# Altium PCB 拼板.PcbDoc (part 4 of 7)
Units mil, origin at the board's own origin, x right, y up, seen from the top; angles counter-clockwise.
Board outline 3630.03 x 5330.03 mil, 2 copper layers (Top Layer, Bottom Layer); 416 components, 35 nets, 1936 pads, 800 vias.
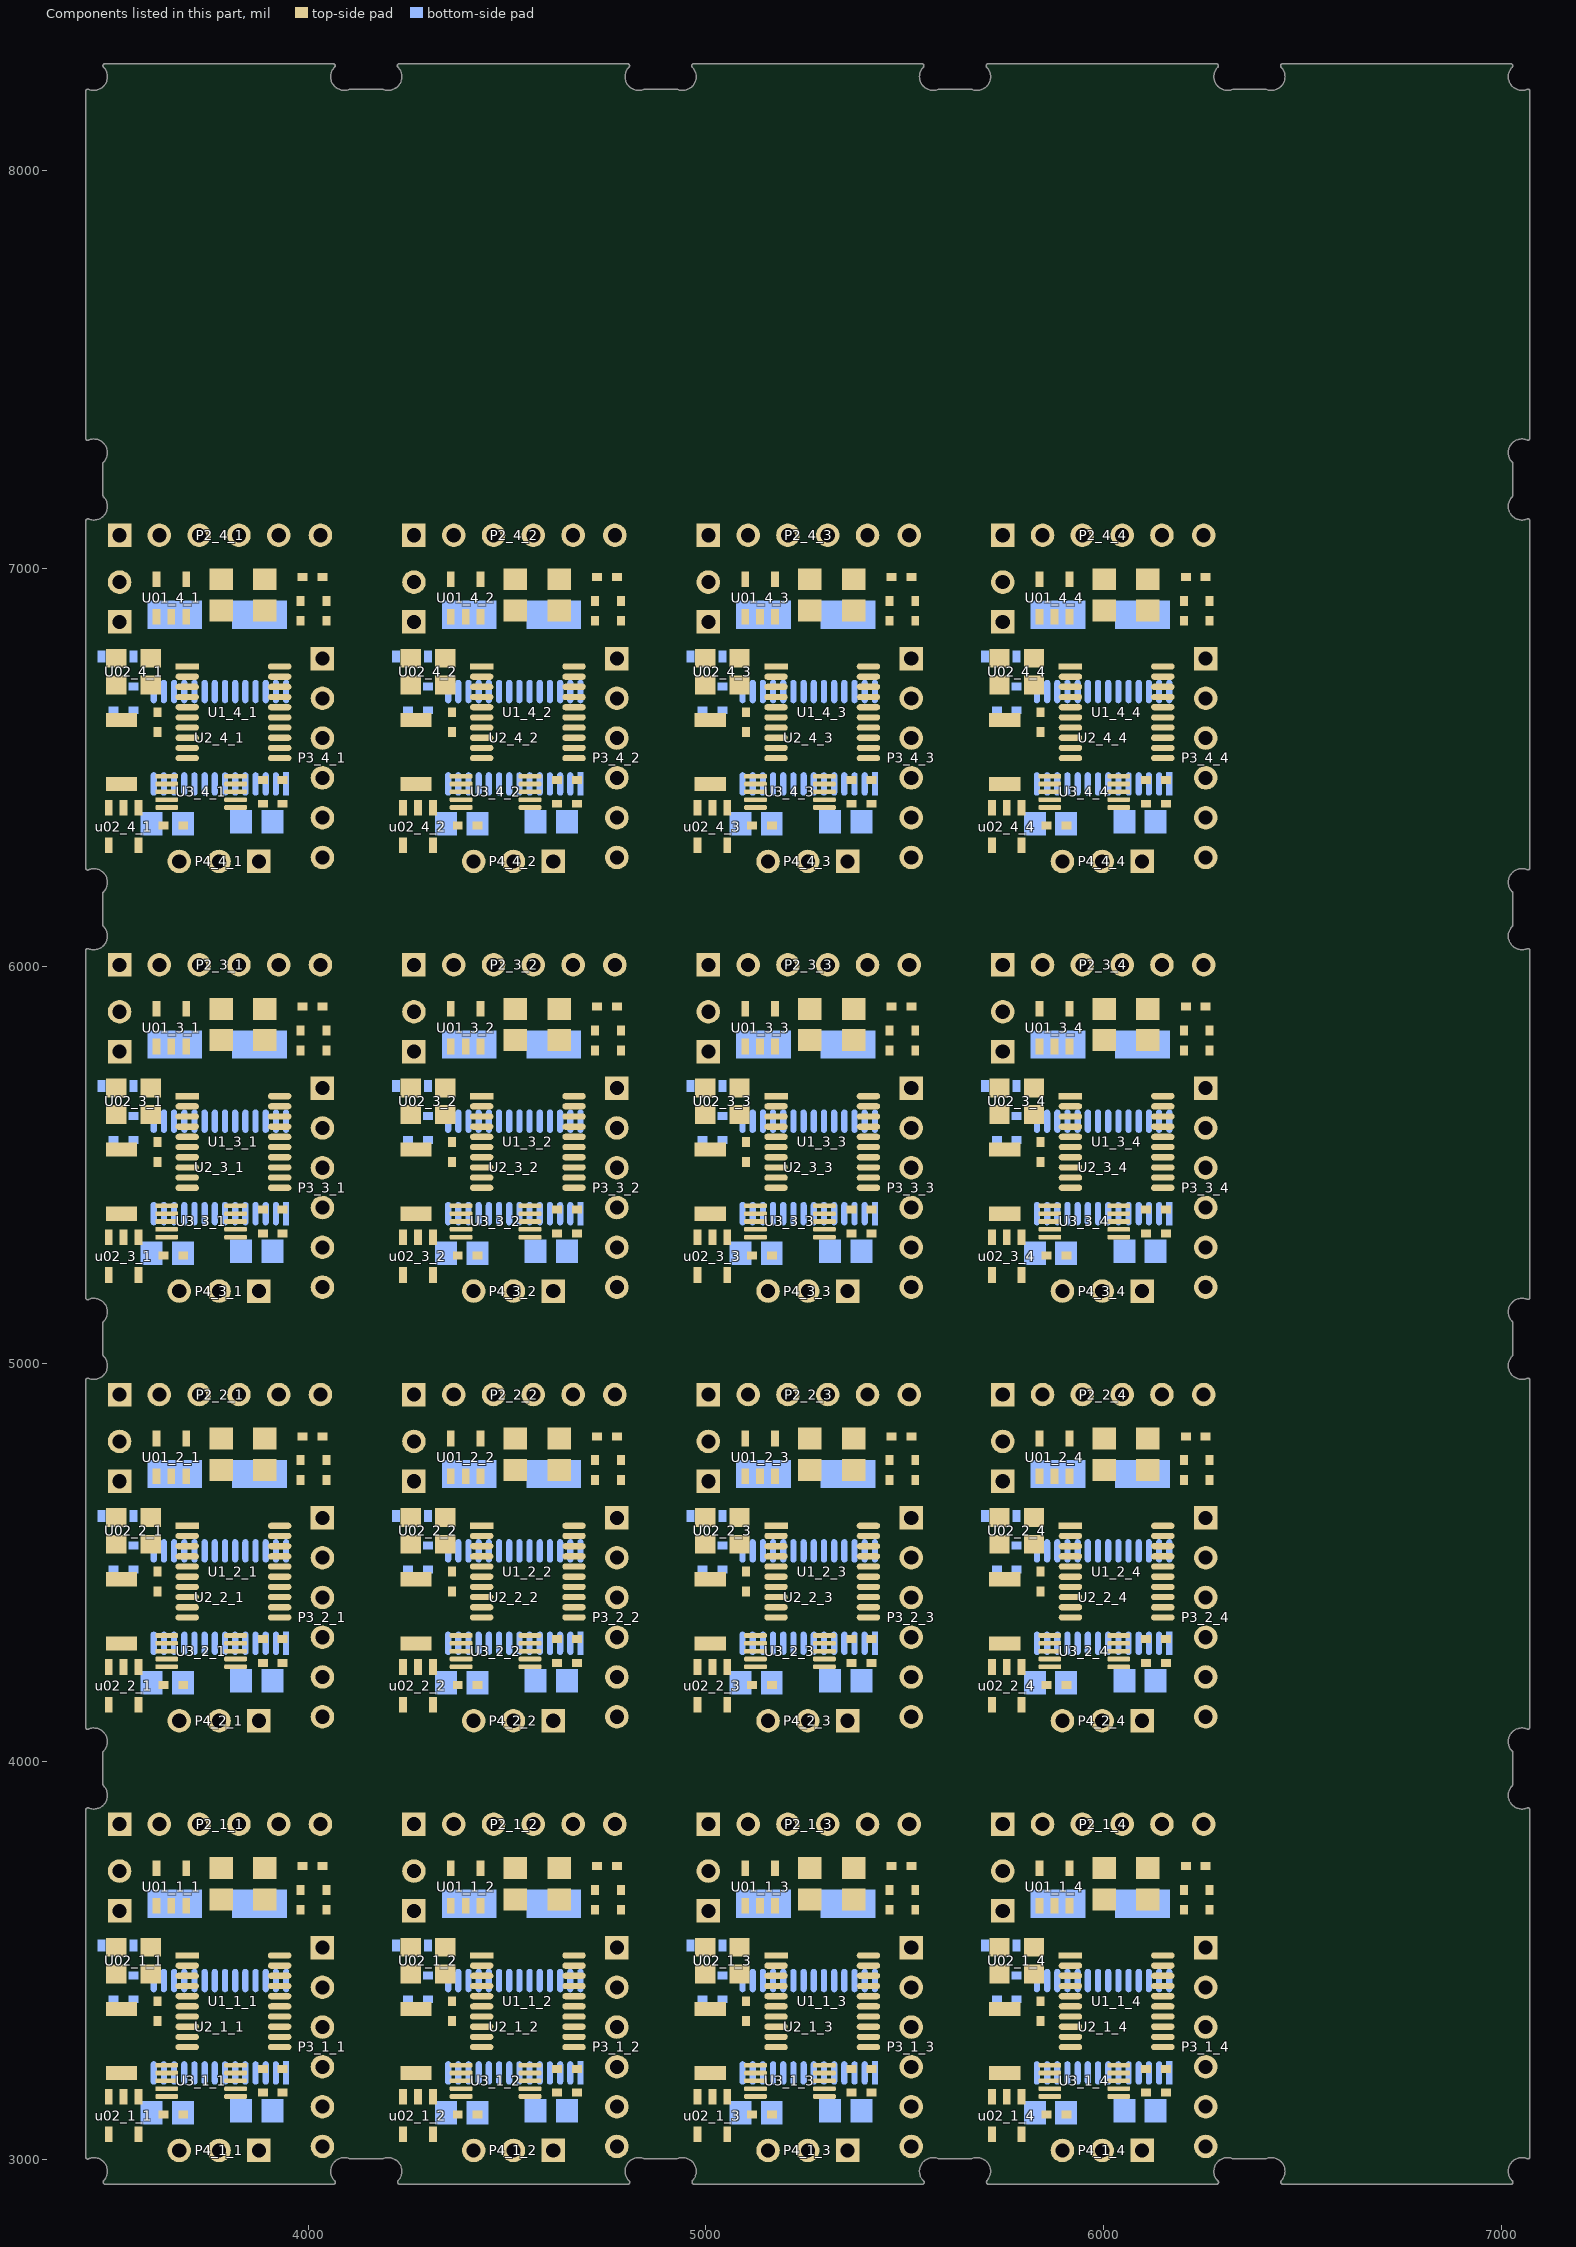
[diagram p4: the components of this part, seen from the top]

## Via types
v1: diameter 24, hole 24, Top Layer to Bottom Layer, 480 vias
v2: diameter 20, hole 10, Top Layer to Bottom Layer, 240 vias
v3: diameter 36, hole 20, Top Layer to Bottom Layer, 48 vias
v4: diameter 32, hole 16, Top Layer to Bottom Layer, 32 vias

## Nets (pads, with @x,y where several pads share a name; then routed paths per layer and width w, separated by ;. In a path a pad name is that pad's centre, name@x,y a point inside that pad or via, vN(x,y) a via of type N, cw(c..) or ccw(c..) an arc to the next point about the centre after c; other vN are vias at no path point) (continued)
copper on no net: (continued)
  Top Layer w16: 3498.66,3158.02 3500.51,3156.18 3500.51,3117.83 3536.07,3082.27 ; 3498.66,4238.02 3500.51,4236.18 3500.51,4197.83 3536.07,4162.27 ; 3498.66,5318.02 3500.51,5316.18 3500.51,5277.83 3536.07,5242.27 ; 3498.66,6398.02 3500.51,6396.18 3500.51,6357.83 3536.07,6322.27 ; 3517.76,3533.57 3519.73,3533.57 3556.35,3570.19 3695.64,3570.19 3779.1,3653.65 3781.07,3653.65 ; 3517.76,4613.57 3519.73,4613.57 3556.35,4650.19 3695.64,4650.19 3779.1,4733.65 3781.07,4733.65 ; 3517.76,5693.57 3519.73,5693.57 3556.35,5730.19 3695.64,5730.19 3779.1,5813.65 3781.07,5813.65 ; 3517.76,6773.57 3519.73,6773.57 3556.35,6810.19 3695.64,6810.19 3779.1,6893.65 3781.07,6893.65 ; 3531.07,3217.31 3531.26,3217.51 3536.07,3217.51 3596.07,3217.51 ; 3531.07,4297.31 3531.26,4297.51 3536.07,4297.51 3596.07,4297.51 ; 3531.07,5377.31 3531.26,5377.51 3536.07,5377.51 3596.07,5377.51 ; 3531.07,6457.31 3531.26,6457.51 3536.07,6457.51 3596.07,6457.51 ; 3535.69,3082.64 3571.63,3118.58 3571.63,3156.18 3573.47,3158.02 ; 3535.69,4162.64 3571.63,4198.58 3571.63,4236.18 3573.47,4238.02 ; 3535.69,5242.64 3571.63,5278.58 3571.63,5316.18 3573.47,5318.02 ; 3535.69,6322.64 3571.63,6358.58 3571.63,6396.18 3573.47,6398.02 ; 3536.07,3078.02 3536.07,3035.22 3598.27,2973.02 3906.07,2973.02 ; 3536.07,4158.02 3536.07,4115.22 3598.27,4053.02 3906.07,4053.02 ; 3536.07,5238.02 3536.07,5195.22 3598.27,5133.02 3906.07,5133.02 ; 3536.07,6318.02 3536.07,6275.22 3598.27,6213.02 3906.07,6213.02 ; 3618.66,3732.51 3618.66,3742.35 3649.33,3773.02 3738.47,3773.02 3779.1,3732.39 3781.07,3732.39 ; 3618.66,4812.51 3618.66,4822.35 3649.33,4853.02 3738.47,4853.02 3779.1,4812.39 3781.07,4812.39 ; 3618.66,5892.51 3618.66,5902.35 3649.33,5933.02 3738.47,5933.02 3779.1,5892.39 3781.07,5892.39 ; 3618.66,6972.51 3618.66,6982.35 3649.33,7013.02 3738.47,7013.02 3779.1,6972.39 3781.07,6972.39 ; 3623.91,3179.12 3612.25,3179.12 3602.91,3188.46 3602.91,3210.67 3596.07,3217.51 ; 3623.91,3217.51 3596.07,3217.51 ; 3623.91,4259.12 3612.25,4259.12 3602.91,4268.46 3602.91,4290.67 3596.07,4297.51 ; 3623.91,4297.51 3596.07,4297.51 ; 3623.91,5339.12 3612.25,5339.12 3602.91,5348.46 3602.91,5370.67 3596.07,5377.51 ; 3623.91,5377.51 3596.07,5377.51 ; 3623.91,6419.12 3612.25,6419.12 3602.91,6428.46 3602.91,6450.67 3596.07,6457.51 ; 3623.91,6457.51 3596.07,6457.51 ; 3665,3177.56 3676.65,3177.56 3686,3168.21 3686,3113.09 3686.07,3113.02 3688.07,3115.02 3703.26,3115.02 3785.48,3197.24 3790.63,3197.24 ; 3665,3198.56 3686.25,3198.56 3708.25,3176.56 v4(3713.77,3176.56) ; 3665,4257.56 3676.65,4257.56 3686,4248.21 3686,4193.09 3686.07,4193.02 3688.07,4195.02 3703.26,4195.02 3785.48,4277.24 3790.63,4277.24 ; 3665,4278.56 3686.25,4278.56 3708.25,4256.56 v4(3713.77,4256.56) ; 3665,5337.56 3676.65,5337.56 3686,5328.21 3686,5273.09 3686.07,5273.02 3688.07,5275.02 3703.26,5275.02 3785.48,5357.24 3790.63,5357.24 ; 3665,5358.56 3686.25,5358.56 3708.25,5336.56 v4(3713.77,5336.56) ; 3665,6417.56 3676.65,6417.56 3686,6408.21 3686,6353.09 3686.07,6353.02 3688.07,6355.02 3703.26,6355.02 3785.48,6437.24 3790.63,6437.24 ; 3665,6438.56 3686.25,6438.56 3708.25,6416.56 v4(3713.77,6416.56) ; 3696.07,3436.25 3696.19,3436.38 3733.08,3436.38 3778.07,3481.36 3778.07,3650.65 3781.07,3653.65 ; 3696.07,4516.25 3696.19,4516.38 3733.08,4516.38 3778.07,4561.36 3778.07,4730.65 3781.07,4733.65 ; 3696.07,5596.25 3696.19,5596.38 3733.08,5596.38 3778.07,5641.36 3778.07,5810.65 3781.07,5813.65 ; 3696.07,6676.25 3696.19,6676.38 3733.08,6676.38 3778.07,6721.36 3778.07,6890.65 3781.07,6893.65 ; v4(3831.07,3128.02) 3834.13,3131.08 3841.22,3131.08 3860.57,3150.43 3860.57,3168.65 3851.19,3178.02 3841.07,3178.02 ; v4(3831.07,4208.02) 3834.13,4211.08 3841.22,4211.08 3860.57,4230.43 3860.57,4248.65 3851.19,4258.02 3841.07,4258.02 ; v4(3831.07,5288.02) 3834.13,5291.08 3841.22,5291.08 3860.57,5310.43 3860.57,5328.65 3851.19,5338.02 3841.07,5338.02 ; v4(3831.07,6368.02) 3834.13,6371.08 3841.22,6371.08 3860.57,6390.43 3860.57,6408.65 3851.19,6418.02 3841.07,6418.02 ; 3891.07,3732.39 3893.03,3732.39 3995.43,3834.78 4022.83,3834.78 4031.07,3843.02 ; 3891.07,4812.39 3893.03,4812.39 3995.43,4914.78 4022.83,4914.78 4031.07,4923.02 ; 3891.07,5892.39 3893.03,5892.39 3995.43,5994.78 4022.83,5994.78 4031.07,6003.02 ; 3891.07,6972.39 3893.03,6972.39 3995.43,7074.78 4022.83,7074.78 4031.07,7083.02 ; 3911.07,2973.02 3981.07,2973.02 4036.07,3028.02 ; 3911.07,4053.02 3981.07,4053.02 4036.07,4108.02 ; 3911.07,5133.02 3981.07,5133.02 4036.07,5188.02 ; 3911.07,6213.02 3981.07,6213.02 4036.07,6268.02 ; 4036.07,3033.02 4088.07,3085.02 4088.07,3158.02 4088.07,3733.02 4061.07,3760.02 4061.07,3761.02 4011.57,3761.02 3990.57,3740.02 3988.07,3740.02 3986.07,3738.02 3983.57,3738.02 3981.07,3735.52 3981.07,3675.52 3979.07,3673.52 3976.57,3673.52 3956.7,3653.65 3891.07,3653.65 3781.07,3653.65 ; 4036.07,4113.02 4088.07,4165.02 4088.07,4238.02 4088.07,4813.02 4061.07,4840.02 4061.07,4841.02 4011.57,4841.02 3990.57,4820.02 3988.07,4820.02 3986.07,4818.02 3983.57,4818.02 3981.07,4815.52 3981.07,4755.52 3979.07,4753.52 3976.57,4753.52 3956.7,4733.65 3891.07,4733.65 3781.07,4733.65 ; 4036.07,5193.02 4088.07,5245.02 4088.07,5318.02 4088.07,5893.02 4061.07,5920.02 4061.07,5921.02 4011.57,5921.02 3990.57,5900.02 3988.07,5900.02 3986.07,5898.02 3983.57,5898.02 3981.07,5895.52 3981.07,5835.52 3979.07,5833.52 3976.57,5833.52 3956.7,5813.65 3891.07,5813.65 3781.07,5813.65 ; 4036.07,6273.02 4088.07,6325.02 4088.07,6398.02 4088.07,6973.02 4061.07,7000.02 4061.07,7001.02 4011.57,7001.02 3990.57,6980.02 3988.07,6980.02 3986.07,6978.02 3983.57,6978.02 3981.07,6975.52 3981.07,6915.52 3979.07,6913.52 3976.57,6913.52 3956.7,6893.65 3891.07,6893.65 3781.07,6893.65 ; 4238.66,3158.02 4240.51,3156.18 4240.51,3117.83 4276.07,3082.27 ; 4238.66,4238.02 4240.51,4236.18 4240.51,4197.83 4276.07,4162.27 ; 4238.66,5318.02 4240.51,5316.18 4240.51,5277.83 4276.07,5242.27 ; 4238.66,6398.02 4240.51,6396.18 4240.51,6357.83 4276.07,6322.27 ; 4257.76,3533.57 4259.73,3533.57 4296.35,3570.19 4435.64,3570.19 4519.1,3653.65 4521.07,3653.65 ; 4257.76,4613.57 4259.73,4613.57 4296.35,4650.19 4435.64,4650.19 4519.1,4733.65 4521.07,4733.65 ; 4257.76,5693.57 4259.73,5693.57 4296.35,5730.19 4435.64,5730.19 4519.1,5813.65 4521.07,5813.65 ; 4257.76,6773.57 4259.73,6773.57 4296.35,6810.19 4435.64,6810.19 4519.1,6893.65 4521.07,6893.65 ; 4271.07,3217.31 4271.26,3217.51 4276.07,3217.51 4336.07,3217.51 ; 4271.07,4297.31 4271.26,4297.51 4276.07,4297.51 4336.07,4297.51 ; 4271.07,5377.31 4271.26,5377.51 4276.07,5377.51 4336.07,5377.51 ; 4271.07,6457.31 4271.26,6457.51 4276.07,6457.51 4336.07,6457.51 ; 4275.69,3082.64 4311.63,3118.58 4311.63,3156.18 4313.47,3158.02 ; 4275.69,4162.64 4311.63,4198.58 4311.63,4236.18 4313.47,4238.02 ; 4275.69,5242.64 4311.63,5278.58 4311.63,5316.18 4313.47,5318.02 ; 4275.69,6322.64 4311.63,6358.58 4311.63,6396.18 4313.47,6398.02 ; 4276.07,3078.02 4276.07,3035.22 4338.27,2973.02 4646.07,2973.02 ; 4276.07,4158.02 4276.07,4115.22 4338.27,4053.02 4646.07,4053.02 ; 4276.07,5238.02 4276.07,5195.22 4338.27,5133.02 4646.07,5133.02 ; 4276.07,6318.02 4276.07,6275.22 4338.27,6213.02 4646.07,6213.02 ; 4358.66,3732.51 4358.66,3742.35 4389.33,3773.02 4478.47,3773.02 4519.1,3732.39 4521.07,3732.39 ; 4358.66,4812.51 4358.66,4822.35 4389.33,4853.02 4478.47,4853.02 4519.1,4812.39 4521.07,4812.39 ; 4358.66,5892.51 4358.66,5902.35 4389.33,5933.02 4478.47,5933.02 4519.1,5892.39 4521.07,5892.39 ; 4358.66,6972.51 4358.66,6982.35 4389.33,7013.02 4478.47,7013.02 4519.1,6972.39 4521.07,6972.39 ; 4363.91,3179.12 4352.25,3179.12 4342.91,3188.46 4342.91,3210.67 4336.07,3217.51 ; 4363.91,3217.51 4336.07,3217.51 ; 4363.91,4259.12 4352.25,4259.12 4342.91,4268.46 4342.91,4290.67 4336.07,4297.51 ; 4363.91,4297.51 4336.07,4297.51 ; 4363.91,5339.12 4352.25,5339.12 4342.91,5348.46 4342.91,5370.67 4336.07,5377.51 ; 4363.91,5377.51 4336.07,5377.51 ; 4363.91,6419.12 4352.25,6419.12 4342.91,6428.46 4342.91,6450.67 4336.07,6457.51 ; 4363.91,6457.51 4336.07,6457.51 ; 4405,3177.56 4416.65,3177.56 4426,3168.21 4426,3113.09 4426.07,3113.02 4428.07,3115.02 4443.26,3115.02 4525.48,3197.24 4530.63,3197.24 ; 4405,3198.56 4426.25,3198.56 4448.25,3176.56 v4(4453.77,3176.56) ; 4405,4257.56 4416.65,4257.56 4426,4248.21 4426,4193.09 4426.07,4193.02 4428.07,4195.02 4443.26,4195.02 4525.48,4277.24 4530.63,4277.24 ; 4405,4278.56 4426.25,4278.56 4448.25,4256.56 v4(4453.77,4256.56) ; 4405,5337.56 4416.65,5337.56 4426,5328.21 4426,5273.09 4426.07,5273.02 4428.07,5275.02 4443.26,5275.02 4525.48,5357.24 4530.63,5357.24 ; 4405,5358.56 4426.25,5358.56 4448.25,5336.56 v4(4453.77,5336.56) ; 4405,6417.56 4416.65,6417.56 4426,6408.21 4426,6353.09 4426.07,6353.02 4428.07,6355.02 4443.26,6355.02 4525.48,6437.24 4530.63,6437.24 ; 4405,6438.56 4426.25,6438.56 4448.25,6416.56 v4(4453.77,6416.56) ; 4436.07,3436.25 4436.19,3436.38 4473.08,3436.38 4518.07,3481.36 4518.07,3650.65 4521.07,3653.65 ; 4436.07,4516.25 4436.19,4516.38 4473.08,4516.38 4518.07,4561.36 4518.07,4730.65 4521.07,4733.65 ; 4436.07,5596.25 4436.19,5596.38 4473.08,5596.38 4518.07,5641.36 4518.07,5810.65 4521.07,5813.65 ; 4436.07,6676.25 4436.19,6676.38 4473.08,6676.38 4518.07,6721.36 4518.07,6890.65 4521.07,6893.65 ; v4(4571.07,3128.02) 4574.13,3131.08 4581.22,3131.08 4600.57,3150.43 4600.57,3168.65 4591.19,3178.02 4581.07,3178.02 ; v4(4571.07,4208.02) 4574.13,4211.08 4581.22,4211.08 4600.57,4230.43 4600.57,4248.65 4591.19,4258.02 4581.07,4258.02 ; v4(4571.07,5288.02) 4574.13,5291.08 4581.22,5291.08 4600.57,5310.43 4600.57,5328.65 4591.19,5338.02 4581.07,5338.02 ; v4(4571.07,6368.02) 4574.13,6371.08 4581.22,6371.08 4600.57,6390.43 4600.57,6408.65 4591.19,6418.02 4581.07,6418.02 ; 4631.07,3732.39 4633.03,3732.39 4735.43,3834.78 4762.83,3834.78 4771.07,3843.02 ; 4631.07,4812.39 4633.03,4812.39 4735.43,4914.78 4762.83,4914.78 4771.07,4923.02 ; 4631.07,5892.39 4633.03,5892.39 4735.43,5994.78 4762.83,5994.78 4771.07,6003.02 ; 4631.07,6972.39 4633.03,6972.39 4735.43,7074.78 4762.83,7074.78 4771.07,7083.02 ; 4651.07,2973.02 4721.07,2973.02 4776.07,3028.02 ; 4651.07,4053.02 4721.07,4053.02 4776.07,4108.02 ; 4651.07,5133.02 4721.07,5133.02 4776.07,5188.02 ; 4651.07,6213.02 4721.07,6213.02 4776.07,6268.02 ; 4776.07,3033.02 4828.07,3085.02 4828.07,3158.02 4828.07,3733.02 4801.07,3760.02 4801.07,3761.02 4751.57,3761.02 4730.57,3740.02 4728.07,3740.02 4726.07,3738.02 4723.57,3738.02 4721.07,3735.52 4721.07,3675.52 4719.07,3673.52 4716.57,3673.52 4696.7,3653.65 4631.07,3653.65 4521.07,3653.65 ; 4776.07,4113.02 4828.07,4165.02 4828.07,4238.02 4828.07,4813.02 4801.07,4840.02 4801.07,4841.02 4751.57,4841.02 4730.57,4820.02 4728.07,4820.02 4726.07,4818.02 4723.57,4818.02 4721.07,4815.52 4721.07,4755.52 4719.07,4753.52 4716.57,4753.52 4696.7,4733.65 4631.07,4733.65 4521.07,4733.65 ; 4776.07,5193.02 4828.07,5245.02 4828.07,5318.02 4828.07,5893.02 4801.07,5920.02 4801.07,5921.02 4751.57,5921.02 4730.57,5900.02 4728.07,5900.02 4726.07,5898.02 4723.57,5898.02 4721.07,5895.52 4721.07,5835.52 4719.07,5833.52 4716.57,5833.52 4696.7,5813.65 4631.07,5813.65 4521.07,5813.65 ; 4776.07,6273.02 4828.07,6325.02 4828.07,6398.02 4828.07,6973.02 4801.07,7000.02 4801.07,7001.02 4751.57,7001.02 4730.57,6980.02 4728.07,6980.02 4726.07,6978.02 4723.57,6978.02 4721.07,6975.52 4721.07,6915.52 4719.07,6913.52 4716.57,6913.52 4696.7,6893.65 4631.07,6893.65 4521.07,6893.65 ; 4978.66,3158.02 4980.51,3156.18 4980.51,3117.83 5016.07,3082.27 ; 4978.66,4238.02 4980.51,4236.18 4980.51,4197.83 5016.07,4162.27 ; 4978.66,5318.02 4980.51,5316.18 4980.51,5277.83 5016.07,5242.27 ; 4978.66,6398.02 4980.51,6396.18 4980.51,6357.83 5016.07,6322.27 ; 4997.76,3533.57 4999.73,3533.57 5036.35,3570.19 5175.64,3570.19 5259.1,3653.65 5261.07,3653.65 ; 4997.76,4613.57 4999.73,4613.57 5036.35,4650.19 5175.64,4650.19 5259.1,4733.65 5261.07,4733.65 ; 4997.76,5693.57 4999.73,5693.57 5036.35,5730.19 5175.64,5730.19 5259.1,5813.65 5261.07,5813.65 ; 4997.76,6773.57 4999.73,6773.57 5036.35,6810.19 5175.64,6810.19 5259.1,6893.65 5261.07,6893.65 ; 5011.07,3217.31 5011.26,3217.51 5016.07,3217.51 5076.07,3217.51 ; 5011.07,4297.31 5011.26,4297.51 5016.07,4297.51 5076.07,4297.51 ; 5011.07,5377.31 5011.26,5377.51 5016.07,5377.51 5076.07,5377.51 ; 5011.07,6457.31 5011.26,6457.51 5016.07,6457.51 5076.07,6457.51 ; 5015.69,3082.64 5051.63,3118.58 5051.63,3156.18 5053.47,3158.02 ; 5015.69,4162.64 5051.63,4198.58 5051.63,4236.18 5053.47,4238.02 ; 5015.69,5242.64 5051.63,5278.58 5051.63,5316.18 5053.47,5318.02 ; 5015.69,6322.64 5051.63,6358.58 5051.63,6396.18 5053.47,6398.02 ; 5016.07,3078.02 5016.07,3035.22 5078.27,2973.02 5386.07,2973.02 ; 5016.07,4158.02 5016.07,4115.22 5078.27,4053.02 5386.07,4053.02 ; 5016.07,5238.02 5016.07,5195.22 5078.27,5133.02 5386.07,5133.02 ; 5016.07,6318.02 5016.07,6275.22 5078.27,6213.02 5386.07,6213.02 ; 5098.66,3732.51 5098.66,3742.35 5129.33,3773.02 5218.47,3773.02 5259.1,3732.39 5261.07,3732.39 ; 5098.66,4812.51 5098.66,4822.35 5129.33,4853.02 5218.47,4853.02 5259.1,4812.39 5261.07,4812.39 ; 5098.66,5892.51 5098.66,5902.35 5129.33,5933.02 5218.47,5933.02 5259.1,5892.39 5261.07,5892.39 ; 5098.66,6972.51 5098.66,6982.35 5129.33,7013.02 5218.47,7013.02 5259.1,6972.39 5261.07,6972.39 ; 5103.91,3179.12 5092.25,3179.12 5082.91,3188.46 5082.91,3210.67 5076.07,3217.51 ; 5103.91,3217.51 5076.07,3217.51 ; 5103.91,4259.12 5092.25,4259.12 5082.91,4268.46 5082.91,4290.67 5076.07,4297.51 ; 5103.91,4297.51 5076.07,4297.51 ; 5103.91,5339.12 5092.25,5339.12 5082.91,5348.46 5082.91,5370.67 5076.07,5377.51 ; 5103.91,5377.51 5076.07,5377.51 ; 5103.91,6419.12 5092.25,6419.12 5082.91,6428.46 5082.91,6450.67 5076.07,6457.51 ; 5103.91,6457.51 5076.07,6457.51 ; 5145,3177.56 5156.65,3177.56 5166,3168.21 5166,3113.09 5166.07,3113.02 5168.07,3115.02 5183.26,3115.02 5265.48,3197.24 5270.63,3197.24 ; 5145,3198.56 5166.25,3198.56 5188.25,3176.56 v4(5193.77,3176.56) ; 5145,4257.56 5156.65,4257.56 5166,4248.21 5166,4193.09 5166.07,4193.02 5168.07,4195.02 5183.26,4195.02 5265.48,4277.24 5270.63,4277.24 ; 5145,4278.56 5166.25,4278.56 5188.25,4256.56 v4(5193.77,4256.56) ; 5145,5337.56 5156.65,5337.56 5166,5328.21 5166,5273.09 5166.07,5273.02 5168.07,5275.02 5183.26,5275.02 5265.48,5357.24 5270.63,5357.24 ; 5145,5358.56 5166.25,5358.56 5188.25,5336.56 v4(5193.77,5336.56) ; 5145,6417.56 5156.65,6417.56 5166,6408.21 5166,6353.09 5166.07,6353.02 5168.07,6355.02 5183.26,6355.02 5265.48,6437.24 5270.63,6437.24 ; 5145,6438.56 5166.25,6438.56 5188.25,6416.56 v4(5193.77,6416.56) ; 5176.07,3436.25 5176.19,3436.38 5213.08,3436.38 5258.07,3481.36 5258.07,3650.65 5261.07,3653.65 ; 5176.07,4516.25 5176.19,4516.38 5213.08,4516.38 5258.07,4561.36 5258.07,4730.65 5261.07,4733.65 ; 5176.07,5596.25 5176.19,5596.38 5213.08,5596.38 5258.07,5641.36 5258.07,5810.65 5261.07,5813.65 ; 5176.07,6676.25 5176.19,6676.38 5213.08,6676.38 5258.07,6721.36 5258.07,6890.65 5261.07,6893.65 ; v4(5311.07,3128.02) 5314.13,3131.08 5321.22,3131.08 5340.57,3150.43 5340.57,3168.65 5331.19,3178.02 5321.07,3178.02 ; v4(5311.07,4208.02) 5314.13,4211.08 5321.22,4211.08 5340.57,4230.43 5340.57,4248.65 5331.19,4258.02 5321.07,4258.02 ; v4(5311.07,5288.02) 5314.13,5291.08 5321.22,5291.08 5340.57,5310.43 5340.57,5328.65 5331.19,5338.02 5321.07,5338.02 ; v4(5311.07,6368.02) 5314.13,6371.08 5321.22,6371.08 5340.57,6390.43 5340.57,6408.65 5331.19,6418.02 5321.07,6418.02 ; 5371.07,3732.39 5373.03,3732.39 5475.43,3834.78 5502.83,3834.78 5511.07,3843.02 ; 5371.07,4812.39 5373.03,4812.39 5475.43,4914.78 5502.83,4914.78 5511.07,4923.02 ; 5371.07,5892.39 5373.03,5892.39 5475.43,5994.78 5502.83,5994.78 5511.07,6003.02 ; 5371.07,6972.39 5373.03,6972.39 5475.43,7074.78 5502.83,7074.78 5511.07,7083.02 ; 5391.07,2973.02 5461.07,2973.02 5516.07,3028.02 ; 5391.07,4053.02 5461.07,4053.02 5516.07,4108.02 ; 5391.07,5133.02 5461.07,5133.02 5516.07,5188.02 ; 5391.07,6213.02 5461.07,6213.02 5516.07,6268.02 ; 5516.07,3033.02 5568.07,3085.02 5568.07,3158.02 5568.07,3733.02 5541.07,3760.02 5541.07,3761.02 5491.57,3761.02 5470.57,3740.02 5468.07,3740.02 5466.07,3738.02 5463.57,3738.02 5461.07,3735.52 5461.07,3675.52 5459.07,3673.52 5456.57,3673.52 5436.7,3653.65 5371.07,3653.65 5261.07,3653.65 ; 5516.07,4113.02 5568.07,4165.02 5568.07,4238.02 5568.07,4813.02 5541.07,4840.02 5541.07,4841.02 5491.57,4841.02 5470.57,4820.02 5468.07,4820.02 5466.07,4818.02 5463.57,4818.02 5461.07,4815.52 5461.07,4755.52 5459.07,4753.52 5456.57,4753.52 5436.7,4733.65 5371.07,4733.65 5261.07,4733.65 ; 5516.07,5193.02 5568.07,5245.02 5568.07,5318.02 5568.07,5893.02 5541.07,5920.02 5541.07,5921.02 5491.57,5921.02 5470.57,5900.02 5468.07,5900.02 5466.07,5898.02 5463.57,5898.02 5461.07,5895.52 5461.07,5835.52 5459.07,5833.52 5456.57,5833.52 5436.7,5813.65 5371.07,5813.65 5261.07,5813.65 ; 5516.07,6273.02 5568.07,6325.02 5568.07,6398.02 5568.07,6973.02 5541.07,7000.02 5541.07,7001.02 5491.57,7001.02 5470.57,6980.02 5468.07,6980.02 5466.07,6978.02 5463.57,6978.02 5461.07,6975.52 5461.07,6915.52 5459.07,6913.52 5456.57,6913.52 5436.7,6893.65 5371.07,6893.65 5261.07,6893.65 ; 5718.66,3158.02 5720.51,3156.18 5720.51,3117.83 5756.07,3082.27 ; 5718.66,4238.02 5720.51,4236.18 5720.51,4197.83 5756.07,4162.27 ; 5718.66,5318.02 5720.51,5316.18 5720.51,5277.83 5756.07,5242.27 ; 5718.66,6398.02 5720.51,6396.18 5720.51,6357.83 5756.07,6322.27 ; 5737.76,3533.57 5739.73,3533.57 5776.35,3570.19 5915.64,3570.19 5999.1,3653.65 6001.07,3653.65 ; 5737.76,4613.57 5739.73,4613.57 5776.35,4650.19 5915.64,4650.19 5999.1,4733.65 6001.07,4733.65 ; 5737.76,5693.57 5739.73,5693.57 5776.35,5730.19 5915.64,5730.19 5999.1,5813.65 6001.07,5813.65 ; 5737.76,6773.57 5739.73,6773.57 5776.35,6810.19 5915.64,6810.19 5999.1,6893.65 6001.07,6893.65 ; 5751.07,3217.31 5751.26,3217.51 5756.07,3217.51 5816.07,3217.51 ; 5751.07,4297.31 5751.26,4297.51 5756.07,4297.51 5816.07,4297.51 ; 5751.07,5377.31 5751.26,5377.51 5756.07,5377.51 5816.07,5377.51 ; 5751.07,6457.31 5751.26,6457.51 5756.07,6457.51 5816.07,6457.51 ; 5755.69,3082.64 5791.63,3118.58 5791.63,3156.18 5793.47,3158.02 ; 5755.69,4162.64 5791.63,4198.58 5791.63,4236.18 5793.47,4238.02 ; 5755.69,5242.64 5791.63,5278.58 5791.63,5316.18 5793.47,5318.02 ; 5755.69,6322.64 5791.63,6358.58 5791.63,6396.18 5793.47,6398.02 ; 5756.07,3078.02 5756.07,3035.22 5818.27,2973.02 6126.07,2973.02 ; 5756.07,4158.02 5756.07,4115.22 5818.27,4053.02 6126.07,4053.02 ; 5756.07,5238.02 5756.07,5195.22 5818.27,5133.02 6126.07,5133.02 ; 5756.07,6318.02 5756.07,6275.22 5818.27,6213.02 6126.07,6213.02 ; 5838.66,3732.51 5838.66,3742.35 5869.33,3773.02 5958.47,3773.02 5999.1,3732.39 6001.07,3732.39 ; 5838.66,4812.51 5838.66,4822.35 5869.33,4853.02 5958.47,4853.02 5999.1,4812.39 6001.07,4812.39 ; 5838.66,5892.51 5838.66,5902.35 5869.33,5933.02 5958.47,5933.02 5999.1,5892.39 6001.07,5892.39 ; 5838.66,6972.51 5838.66,6982.35 5869.33,7013.02 5958.47,7013.02 5999.1,6972.39 6001.07,6972.39 ; 5843.91,3179.12 5832.25,3179.12 5822.91,3188.46 5822.91,3210.67 5816.07,3217.51 ; 5843.91,3217.51 5816.07,3217.51 ; 5843.91,4259.12 5832.25,4259.12 5822.91,4268.46 5822.91,4290.67 5816.07,4297.51 ; 5843.91,4297.51 5816.07,4297.51 ; 5843.91,5339.12 5832.25,5339.12 5822.91,5348.46 5822.91,5370.67 5816.07,5377.51 ; 5843.91,5377.51 5816.07,5377.51 ; 5843.91,6419.12 5832.25,6419.12 5822.91,6428.46 5822.91,6450.67 5816.07,6457.51 ; 5843.91,6457.51 5816.07,6457.51 ; 5885,3177.56 5896.65,3177.56 5906,3168.21 5906,3113.09 5906.07,3113.02 5908.07,3115.02 5923.26,3115.02 6005.48,3197.24 6010.63,3197.24 ; 5885,3198.56 5906.25,3198.56 5928.25,3176.56 v4(5933.77,3176.56) ; 5885,4257.56 5896.65,4257.56 5906,4248.21 5906,4193.09 5906.07,4193.02 5908.07,4195.02 5923.26,4195.02 6005.48,4277.24 6010.63,4277.24 ; 5885,4278.56 5906.25,4278.56 5928.25,4256.56 v4(5933.77,4256.56) ; 5885,5337.56 5896.65,5337.56 5906,5328.21 5906,5273.09 5906.07,5273.02 5908.07,5275.02 5923.26,5275.02 6005.48,5357.24 6010.63,5357.24 ; 5885,5358.56 5906.25,5358.56 5928.25,5336.56 v4(5933.77,5336.56) ; 5885,6417.56 5896.65,6417.56 5906,6408.21 5906,6353.09 5906.07,6353.02 5908.07,6355.02 5923.26,6355.02 6005.48,6437.24 6010.63,6437.24 ; 5885,6438.56 5906.25,6438.56 5928.25,6416.56 v4(5933.77,6416.56) ; 5916.07,3436.25 5916.19,3436.38 5953.08,3436.38 5998.07,3481.36 5998.07,3650.65 6001.07,3653.65 ; 5916.07,4516.25 5916.19,4516.38 5953.08,4516.38 5998.07,4561.36 5998.07,4730.65 6001.07,4733.65 ; 5916.07,5596.25 5916.19,5596.38 5953.08,5596.38 5998.07,5641.36 5998.07,5810.65 6001.07,5813.65 ; 5916.07,6676.25 5916.19,6676.38 5953.08,6676.38 5998.07,6721.36 5998.07,6890.65 6001.07,6893.65 ; v4(6051.07,3128.02) 6054.13,3131.08 6061.22,3131.08 6080.57,3150.43 6080.57,3168.65 6071.19,3178.02 6061.07,3178.02 ; v4(6051.07,4208.02) 6054.13,4211.08 6061.22,4211.08 6080.57,4230.43 6080.57,4248.65 6071.19,4258.02 6061.07,4258.02 ; v4(6051.07,5288.02) 6054.13,5291.08 6061.22,5291.08 6080.57,5310.43 6080.57,5328.65 6071.19,5338.02 6061.07,5338.02 ; v4(6051.07,6368.02) 6054.13,6371.08 6061.22,6371.08 6080.57,6390.43 6080.57,6408.65 6071.19,6418.02 6061.07,6418.02 ; 6111.07,3732.39 6113.03,3732.39 6215.43,3834.78 6242.83,3834.78 6251.07,3843.02 ; 6111.07,4812.39 6113.03,4812.39 6215.43,4914.78 6242.83,4914.78 6251.07,4923.02 ; 6111.07,5892.39 6113.03,5892.39 6215.43,5994.78 6242.83,5994.78 6251.07,6003.02 ; 6111.07,6972.39 6113.03,6972.39 6215.43,7074.78 6242.83,7074.78 6251.07,7083.02 ; 6131.07,2973.02 6201.07,2973.02 6256.07,3028.02 ; 6131.07,4053.02 6201.07,4053.02 6256.07,4108.02 ; 6131.07,5133.02 6201.07,5133.02 6256.07,5188.02 ; 6131.07,6213.02 6201.07,6213.02 6256.07,6268.02 ; 6256.07,3033.02 6308.07,3085.02 6308.07,3158.02 6308.07,3733.02 6281.07,3760.02 6281.07,3761.02 6231.57,3761.02 6210.57,3740.02 6208.07,3740.02 6206.07,3738.02 6203.57,3738.02 6201.07,3735.52 6201.07,3675.52 6199.07,3673.52 6196.57,3673.52 6176.7,3653.65 6111.07,3653.65 6001.07,3653.65 ; 6256.07,4113.02 6308.07,4165.02 6308.07,4238.02 6308.07,4813.02 6281.07,4840.02 6281.07,4841.02 6231.57,4841.02 6210.57,4820.02 6208.07,4820.02 6206.07,4818.02 6203.57,4818.02 6201.07,4815.52 6201.07,4755.52 6199.07,4753.52 6196.57,4753.52 6176.7,4733.65 6111.07,4733.65 6001.07,4733.65 ; 6256.07,5193.02 6308.07,5245.02 6308.07,5318.02 6308.07,5893.02 6281.07,5920.02 6281.07,5921.02 6231.57,5921.02 6210.57,5900.02 6208.07,5900.02 6206.07,5898.02 6203.57,5898.02 6201.07,5895.52 6201.07,5835.52 6199.07,5833.52 6196.57,5833.52 6176.7,5813.65 6111.07,5813.65 6001.07,5813.65 ; 6256.07,6273.02 6308.07,6325.02 6308.07,6398.02 6308.07,6973.02 6281.07,7000.02 6281.07,7001.02 6231.57,7001.02 6210.57,6980.02 6208.07,6980.02 6206.07,6978.02 6203.57,6978.02 6201.07,6975.52 6201.07,6915.52 6199.07,6913.52 6196.57,6913.52 6176.7,6893.65 6111.07,6893.65 6001.07,6893.65
  Top Layer w20: 3476.7,3402.66 3497.78,3423.74 3497.78,3424.73 3560.5,3424.73 3602.4,3466.64 3604.37,3466.64 3606.34,3466.64 3662.32,3410.66 3696.07,3410.66 ; 3476.7,4482.66 3497.78,4503.74 3497.78,4504.73 3560.5,4504.73 3602.4,4546.64 3604.37,4546.64 3606.34,4546.64 3662.32,4490.66 3696.07,4490.66 ; 3476.7,5562.66 3497.78,5583.74 3497.78,5584.73 3560.5,5584.73 3602.4,5626.64 3604.37,5626.64 3606.34,5626.64 3662.32,5570.66 3696.07,5570.66 ; 3476.7,6642.66 3497.78,6663.74 3497.78,6664.73 3560.5,6664.73 3602.4,6706.64 3604.37,6706.64 3606.34,6706.64 3662.32,6650.66 3696.07,6650.66 ; 3526.07,3843.02 3526.07,3725.14 ; 3526.07,4923.02 3526.07,4805.14 ; 3526.07,6003.02 3526.07,5885.14 ; 3526.07,7083.02 3526.07,6965.14 ; 3536.07,3158.02 3536.07,3217.51 3536.07,3263.02 v3(3537.32,3264.27) ; 3536.07,4238.02 3536.07,4297.51 3536.07,4343.02 v3(3537.32,4344.27) ; 3536.07,5318.02 3536.07,5377.51 3536.07,5423.02 v3(3537.32,5424.27) ; 3536.07,6398.02 3536.07,6457.51 3536.07,6503.02 v3(3537.32,6504.27) ; 3621.07,3348.02 3621.07,3345.52 3539.82,3264.27 v3(3537.32,3264.27) ; 3621.07,4428.02 3621.07,4425.52 3539.82,4344.27 v3(3537.32,4344.27) ; 3621.07,5508.02 3621.07,5505.52 3539.82,5424.27 v3(3537.32,5424.27) ; 3621.07,6588.02 3621.07,6585.52 3539.82,6504.27 v3(3537.32,6504.27) ; 3656.07,3638.02 3656.07,3653.27 3631.31,3678.02 3573.18,3678.02 3526.07,3725.14 ; 3656.07,4718.02 3656.07,4733.27 3631.31,4758.02 3573.18,4758.02 3526.07,4805.14 ; 3656.07,5798.02 3656.07,5813.27 3631.31,5838.02 3573.18,5838.02 3526.07,5885.14 ; 3656.07,6878.02 3656.07,6893.27 3631.31,6918.02 3573.18,6918.02 3526.07,6965.14 ; v3(3857.87,3266.02) 3857.87,3261.69 3883.57,3236 3883.57,3228.02 3886.07,3228.02 ; v3(3857.87,4346.02) 3857.87,4341.69 3883.57,4316 3883.57,4308.02 3886.07,4308.02 ; v3(3857.87,5426.02) 3857.87,5421.69 3883.57,5396 3883.57,5388.02 3886.07,5388.02 ; v3(3857.87,6506.02) 3857.87,6501.69 3883.57,6476 3883.57,6468.02 3886.07,6468.02 ; v3(4036.07,3713.02) 4036.07,3690.52 4046.07,3680.52 4046.07,3678.02 ; v3(4036.07,4793.02) 4036.07,4770.52 4046.07,4760.52 4046.07,4758.02 ; v3(4036.07,5873.02) 4036.07,5850.52 4046.07,5840.52 4046.07,5838.02 ; v3(4036.07,6953.02) 4036.07,6930.52 4046.07,6920.52 4046.07,6918.02 ; 4216.7,3402.66 4237.78,3423.74 4237.78,3424.73 4300.5,3424.73 4342.4,3466.64 4344.37,3466.64 4346.34,3466.64 4402.32,3410.66 4436.07,3410.66 ; 4216.7,4482.66 4237.78,4503.74 4237.78,4504.73 4300.5,4504.73 4342.4,4546.64 4344.37,4546.64 4346.34,4546.64 4402.32,4490.66 4436.07,4490.66 ; 4216.7,5562.66 4237.78,5583.74 4237.78,5584.73 4300.5,5584.73 4342.4,5626.64 4344.37,5626.64 4346.34,5626.64 4402.32,5570.66 4436.07,5570.66 ; 4216.7,6642.66 4237.78,6663.74 4237.78,6664.73 4300.5,6664.73 4342.4,6706.64 4344.37,6706.64 4346.34,6706.64 4402.32,6650.66 4436.07,6650.66 ; 4266.07,3843.02 4266.07,3725.14 ; 4266.07,4923.02 4266.07,4805.14 ; 4266.07,6003.02 4266.07,5885.14 ; 4266.07,7083.02 4266.07,6965.14 ; 4276.07,3158.02 4276.07,3217.51 4276.07,3263.02 v3(4277.32,3264.27) ; 4276.07,4238.02 4276.07,4297.51 4276.07,4343.02 v3(4277.32,4344.27) ; 4276.07,5318.02 4276.07,5377.51 4276.07,5423.02 v3(4277.32,5424.27) ; 4276.07,6398.02 4276.07,6457.51 4276.07,6503.02 v3(4277.32,6504.27) ; 4361.07,3348.02 4361.07,3345.52 4279.82,3264.27 v3(4277.32,3264.27) ; 4361.07,4428.02 4361.07,4425.52 4279.82,4344.27 v3(4277.32,4344.27) ; 4361.07,5508.02 4361.07,5505.52 4279.82,5424.27 v3(4277.32,5424.27) ; 4361.07,6588.02 4361.07,6585.52 4279.82,6504.27 v3(4277.32,6504.27) ; 4396.07,3638.02 4396.07,3653.27 4371.31,3678.02 4313.18,3678.02 4266.07,3725.14 ; 4396.07,4718.02 4396.07,4733.27 4371.31,4758.02 4313.18,4758.02 4266.07,4805.14 ; 4396.07,5798.02 4396.07,5813.27 4371.31,5838.02 4313.18,5838.02 4266.07,5885.14 ; 4396.07,6878.02 4396.07,6893.27 4371.31,6918.02 4313.18,6918.02 4266.07,6965.14 ; v3(4597.87,3266.02) 4597.87,3261.69 4623.57,3236 4623.57,3228.02 4626.07,3228.02 ; v3(4597.87,4346.02) 4597.87,4341.69 4623.57,4316 4623.57,4308.02 4626.07,4308.02 ; v3(4597.87,5426.02) 4597.87,5421.69 4623.57,5396 4623.57,5388.02 4626.07,5388.02 ; v3(4597.87,6506.02) 4597.87,6501.69 4623.57,6476 4623.57,6468.02 4626.07,6468.02 ; v3(4776.07,3713.02) 4776.07,3690.52 4786.07,3680.52 4786.07,3678.02 ; v3(4776.07,4793.02) 4776.07,4770.52 4786.07,4760.52 4786.07,4758.02 ; v3(4776.07,5873.02) 4776.07,5850.52 4786.07,5840.52 4786.07,5838.02 ; v3(4776.07,6953.02) 4776.07,6930.52 4786.07,6920.52 4786.07,6918.02 ; 4956.7,3402.66 4977.78,3423.74 4977.78,3424.73 5040.5,3424.73 5082.4,3466.64 5084.37,3466.64 5086.34,3466.64 5142.32,3410.66 5176.07,3410.66 ; 4956.7,4482.66 4977.78,4503.74 4977.78,4504.73 5040.5,4504.73 5082.4,4546.64 5084.37,4546.64 5086.34,4546.64 5142.32,4490.66 5176.07,4490.66 ; 4956.7,5562.66 4977.78,5583.74 4977.78,5584.73 5040.5,5584.73 5082.4,5626.64 5084.37,5626.64 5086.34,5626.64 5142.32,5570.66 5176.07,5570.66 ; 4956.7,6642.66 4977.78,6663.74 4977.78,6664.73 5040.5,6664.73 5082.4,6706.64 5084.37,6706.64 5086.34,6706.64 5142.32,6650.66 5176.07,6650.66 ; 5006.07,3843.02 5006.07,3725.14 ; 5006.07,4923.02 5006.07,4805.14 ; 5006.07,6003.02 5006.07,5885.14 ; 5006.07,7083.02 5006.07,6965.14 ; 5016.07,3158.02 5016.07,3217.51 5016.07,3263.02 v3(5017.32,3264.27) ; 5016.07,4238.02 5016.07,4297.51 5016.07,4343.02 v3(5017.32,4344.27) ; 5016.07,5318.02 5016.07,5377.51 5016.07,5423.02 v3(5017.32,5424.27) ; 5016.07,6398.02 5016.07,6457.51 5016.07,6503.02 v3(5017.32,6504.27) ; 5101.07,3348.02 5101.07,3345.52 5019.82,3264.27 v3(5017.32,3264.27) ; 5101.07,4428.02 5101.07,4425.52 5019.82,4344.27 v3(5017.32,4344.27) ; 5101.07,5508.02 5101.07,5505.52 5019.82,5424.27 v3(5017.32,5424.27) ; 5101.07,6588.02 5101.07,6585.52 5019.82,6504.27 v3(5017.32,6504.27) ; 5136.07,3638.02 5136.07,3653.27 5111.31,3678.02 5053.18,3678.02 5006.07,3725.14 ; 5136.07,4718.02 5136.07,4733.27 5111.31,4758.02 5053.18,4758.02 5006.07,4805.14 ; 5136.07,5798.02 5136.07,5813.27 5111.31,5838.02 5053.18,5838.02 5006.07,5885.14 ; 5136.07,6878.02 5136.07,6893.27 5111.31,6918.02 5053.18,6918.02 5006.07,6965.14 ; v3(5337.87,3266.02) 5337.87,3261.69 5363.57,3236 5363.57,3228.02 5366.07,3228.02 ; v3(5337.87,4346.02) 5337.87,4341.69 5363.57,4316 5363.57,4308.02 5366.07,4308.02 ; v3(5337.87,5426.02) 5337.87,5421.69 5363.57,5396 5363.57,5388.02 5366.07,5388.02 ; v3(5337.87,6506.02) 5337.87,6501.69 5363.57,6476 5363.57,6468.02 5366.07,6468.02 ; v3(5516.07,3713.02) 5516.07,3690.52 5526.07,3680.52 5526.07,3678.02 ; v3(5516.07,4793.02) 5516.07,4770.52 5526.07,4760.52 5526.07,4758.02 ; v3(5516.07,5873.02) 5516.07,5850.52 5526.07,5840.52 5526.07,5838.02 ; v3(5516.07,6953.02) 5516.07,6930.52 5526.07,6920.52 5526.07,6918.02 ; 5696.7,3402.66 5717.78,3423.74 5717.78,3424.73 5780.5,3424.73 5822.4,3466.64 5824.37,3466.64 5826.34,3466.64 5882.32,3410.66 5916.07,3410.66 ; 5696.7,4482.66 5717.78,4503.74 5717.78,4504.73 5780.5,4504.73 5822.4,4546.64 5824.37,4546.64 5826.34,4546.64 5882.32,4490.66 5916.07,4490.66 ; 5696.7,5562.66 5717.78,5583.74 5717.78,5584.73 5780.5,5584.73 5822.4,5626.64 5824.37,5626.64 5826.34,5626.64 5882.32,5570.66 5916.07,5570.66 ; 5696.7,6642.66 5717.78,6663.74 5717.78,6664.73 5780.5,6664.73 5822.4,6706.64 5824.37,6706.64 5826.34,6706.64 5882.32,6650.66 5916.07,6650.66 ; 5746.07,3843.02 5746.07,3725.14 ; 5746.07,4923.02 5746.07,4805.14 ; 5746.07,6003.02 5746.07,5885.14 ; 5746.07,7083.02 5746.07,6965.14 ; 5756.07,3158.02 5756.07,3217.51 5756.07,3263.02 v3(5757.32,3264.27) ; 5756.07,4238.02 5756.07,4297.51 5756.07,4343.02 v3(5757.32,4344.27) ; 5756.07,5318.02 5756.07,5377.51 5756.07,5423.02 v3(5757.32,5424.27) ; 5756.07,6398.02 5756.07,6457.51 5756.07,6503.02 v3(5757.32,6504.27) ; 5841.07,3348.02 5841.07,3345.52 5759.82,3264.27 v3(5757.32,3264.27) ; 5841.07,4428.02 5841.07,4425.52 5759.82,4344.27 v3(5757.32,4344.27) ; 5841.07,5508.02 5841.07,5505.52 5759.82,5424.27 v3(5757.32,5424.27) ; 5841.07,6588.02 5841.07,6585.52 5759.82,6504.27 v3(5757.32,6504.27) ; 5876.07,3638.02 5876.07,3653.27 5851.31,3678.02 5793.18,3678.02 5746.07,3725.14 ; 5876.07,4718.02 5876.07,4733.27 5851.31,4758.02 5793.18,4758.02 5746.07,4805.14 ; 5876.07,5798.02 5876.07,5813.27 5851.31,5838.02 5793.18,5838.02 5746.07,5885.14 ; 5876.07,6878.02 5876.07,6893.27 5851.31,6918.02 5793.18,6918.02 5746.07,6965.14 ; v3(6077.87,3266.02) 6077.87,3261.69 6103.57,3236 6103.57,3228.02 6106.07,3228.02 ; v3(6077.87,4346.02) 6077.87,4341.69 6103.57,4316 6103.57,4308.02 6106.07,4308.02 ; v3(6077.87,5426.02) 6077.87,5421.69 6103.57,5396 6103.57,5388.02 6106.07,5388.02 ; v3(6077.87,6506.02) 6077.87,6501.69 6103.57,6476 6103.57,6468.02 6106.07,6468.02 ; v3(6256.07,3713.02) 6256.07,3690.52 6266.07,3680.52 6266.07,3678.02 ; v3(6256.07,4793.02) 6256.07,4770.52 6266.07,4760.52 6266.07,4758.02 ; v3(6256.07,5873.02) 6256.07,5850.52 6266.07,5840.52 6266.07,5838.02 ; v3(6256.07,6953.02) 6256.07,6930.52 6266.07,6920.52 6266.07,6918.02 ; 3526.07,3725.14 3466.07,3665.14 3466.07,3335.52 v3(3537.32,3264.27) ; 3526.07,4805.14 3466.07,4745.14 3466.07,4415.52 v3(3537.32,4344.27) ; 3526.07,5885.14 3466.07,5825.14 3466.07,5495.52 v3(3537.32,5424.27) ; 3526.07,6965.14 3466.07,6905.14 3466.07,6575.52 v3(3537.32,6504.27) ; 4266.07,3725.14 4206.07,3665.14 4206.07,3335.52 v3(4277.32,3264.27) ; 4266.07,4805.14 4206.07,4745.14 4206.07,4415.52 v3(4277.32,4344.27) ; 4266.07,5885.14 4206.07,5825.14 4206.07,5495.52 v3(4277.32,5424.27) ; 4266.07,6965.14 4206.07,6905.14 4206.07,6575.52 v3(4277.32,6504.27) ; 5006.07,3725.14 4946.07,3665.14 4946.07,3335.52 v3(5017.32,3264.27) ; 5006.07,4805.14 4946.07,4745.14 4946.07,4415.52 v3(5017.32,4344.27) ; 5006.07,5885.14 4946.07,5825.14 4946.07,5495.52 v3(5017.32,5424.27) ; 5006.07,6965.14 4946.07,6905.14 4946.07,6575.52 v3(5017.32,6504.27) ; 5746.07,3725.14 5686.07,3665.14 5686.07,3335.52 v3(5757.32,3264.27) ; 5746.07,4805.14 5686.07,4745.14 5686.07,4415.52 v3(5757.32,4344.27) ; 5746.07,5885.14 5686.07,5825.14 5686.07,5495.52 v3(5757.32,5424.27) ; 5746.07,6965.14 5686.07,6905.14 5686.07,6575.52 v3(5757.32,6504.27)
  Top Layer w30: 3526.07,3625.14 3605.31,3625.14 ; 3526.07,4705.14 3605.31,4705.14 ; 3526.07,5785.14 3605.31,5785.14 ; 3526.07,6865.14 3605.31,6865.14 ; 3618.66,3633.34 3618.66,3625.14 3618.66,3617.61 3637.94,3598.34 3675.89,3598.34 3693.47,3615.91 3693.47,3638.02 ; 3618.66,4713.34 3618.66,4705.14 3618.66,4697.61 3637.94,4678.34 3675.89,4678.34 3693.47,4695.91 3693.47,4718.02 ; 3618.66,5793.34 3618.66,5785.14 3618.66,5777.61 3637.94,5758.34 3675.89,5758.34 3693.47,5775.91 3693.47,5798.02 ; 3618.66,6873.34 3618.66,6865.14 3618.66,6857.61 3637.94,6838.34 3675.89,6838.34 3693.47,6855.91 3693.47,6878.02 ; 4266.07,3625.14 4345.31,3625.14 ; 4266.07,4705.14 4345.31,4705.14 ; 4266.07,5785.14 4345.31,5785.14 ; 4266.07,6865.14 4345.31,6865.14 ; 4358.66,3633.34 4358.66,3625.14 4358.66,3617.61 4377.94,3598.34 4415.89,3598.34 4433.47,3615.91 4433.47,3638.02 ; 4358.66,4713.34 4358.66,4705.14 4358.66,4697.61 4377.94,4678.34 4415.89,4678.34 4433.47,4695.91 4433.47,4718.02 ; 4358.66,5793.34 4358.66,5785.14 4358.66,5777.61 4377.94,5758.34 4415.89,5758.34 4433.47,5775.91 4433.47,5798.02 ; 4358.66,6873.34 4358.66,6865.14 4358.66,6857.61 4377.94,6838.34 4415.89,6838.34 4433.47,6855.91 4433.47,6878.02 ; 5006.07,3625.14 5085.31,3625.14 ; 5006.07,4705.14 5085.31,4705.14 ; 5006.07,5785.14 5085.31,5785.14 ; 5006.07,6865.14 5085.31,6865.14 ; 5098.66,3633.34 5098.66,3625.14 5098.66,3617.61 5117.94,3598.34 5155.89,3598.34 5173.47,3615.91 5173.47,3638.02 ; 5098.66,4713.34 5098.66,4705.14 5098.66,4697.61 5117.94,4678.34 5155.89,4678.34 5173.47,4695.91 5173.47,4718.02 ; 5098.66,5793.34 5098.66,5785.14 5098.66,5777.61 5117.94,5758.34 5155.89,5758.34 5173.47,5775.91 5173.47,5798.02 ; 5098.66,6873.34 5098.66,6865.14 5098.66,6857.61 5117.94,6838.34 5155.89,6838.34 5173.47,6855.91 5173.47,6878.02 ; 5746.07,3625.14 5825.31,3625.14 ; 5746.07,4705.14 5825.31,4705.14 ; 5746.07,5785.14 5825.31,5785.14 ; 5746.07,6865.14 5825.31,6865.14 ; 5838.66,3633.34 5838.66,3625.14 5838.66,3617.61 5857.94,3598.34 5895.89,3598.34 5913.47,3615.91 5913.47,3638.02 ; 5838.66,4713.34 5838.66,4705.14 5838.66,4697.61 5857.94,4678.34 5895.89,4678.34 5913.47,4695.91 5913.47,4718.02 ; 5838.66,5793.34 5838.66,5785.14 5838.66,5777.61 5857.94,5758.34 5895.89,5758.34 5913.47,5775.91 5913.47,5798.02 ; 5838.66,6873.34 5838.66,6865.14 5838.66,6857.61 5857.94,6838.34 5895.89,6838.34 5913.47,6855.91 5913.47,6878.02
